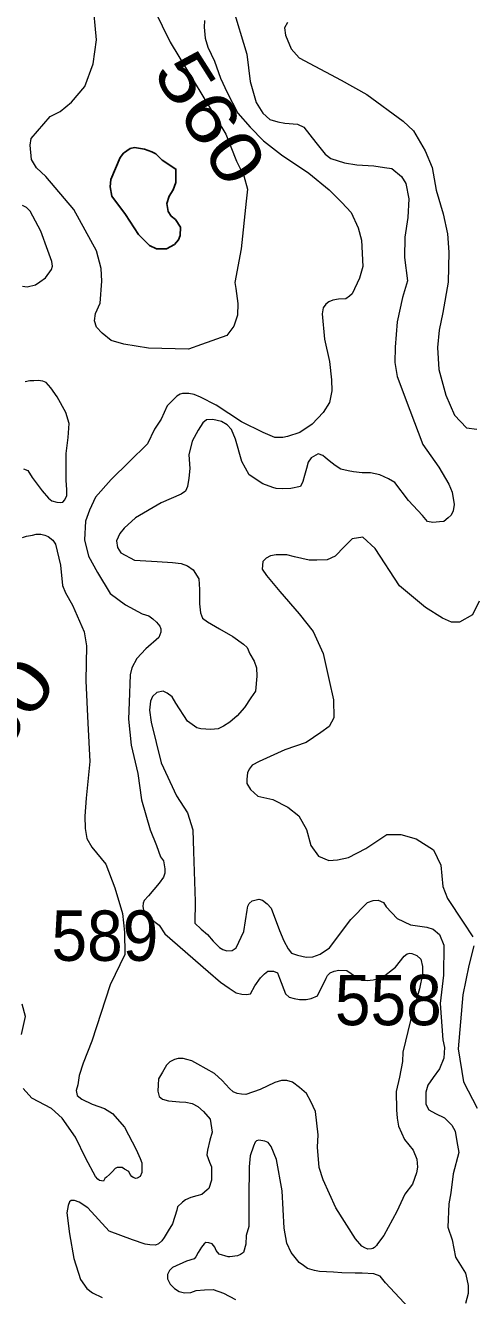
# Model space of a CAD drawing. Extents: x 445.4 to 500, y 8728.7 to 8784.
# Drawn here: x 475.988 to 477.407, y 8763.931 to 8767.967 of the extents above; entities that cross this region are included whole.
import ezdxf
from ezdxf.enums import TextEntityAlignment as Align

# ---------------------------------------------------------------- set-up
doc = ezdxf.new("R2010")
doc.units = 0
doc.header["$LTSCALE"] = 0.064
doc.layers.add('1', color=7, linetype='Continuous', lineweight=25)
doc.layers.add('2', color=7, linetype='Continuous', lineweight=13)
doc.layers.add('21', color=7, linetype='Continuous')
doc.layers.add('61', color=7, linetype='Continuous')

msp = doc.modelspace()

# ---------------------------------------------------------------- linework, layer by layer
at = {"layer": '1'}
msp.add_lwpolyline([(476.2891, 8767.5469), (476.259, 8767.477), (476.2574, 8767.4537), (476.2624, 8767.4237), (476.3058, 8767.3654), (476.3475, 8767.3021), (476.3825, 8767.2671), (476.4042, 8767.2571), (476.4359, 8767.2571), (476.4609, 8767.2704), (476.4742, 8767.2854), (476.4793, 8767.2987), (476.4809, 8767.3254), (476.4642, 8767.3504), (476.4509, 8767.3604), (476.4409, 8767.3754), (476.4375, 8767.4003), (476.4442, 8767.4237), (476.4576, 8767.4437), (476.4659, 8767.467), (476.4659, 8767.4936), (476.4659, 8767.5103), (476.4225, 8767.5386), (476.4025, 8767.5586), (476.3892, 8767.5653), (476.3658, 8767.5736), (476.3341, 8767.5786), (476.3208, 8767.5753), (476.2991, 8767.5603)], close=True, dxfattribs=at)
at = {"layer": '2'}
for points in [[(476.3972, 8768.0175), (476.4473, 8767.9131), (476.6242, 8767.6215), (476.6578, 8767.5353), (476.681, 8767.4884), (476.6927, 8767.4468), (476.6893, 8767.4085), (476.6727, 8767.2569), (476.6526, 8767.1503), (476.656, 8767.1303), (476.6626, 8767.0836), (476.6609, 8767.046), (476.6492, 8767.0111), (476.6275, 8766.9811), (476.5474, 8766.9527), (476.5057, 8766.9378), (476.3789, 8766.9411), (476.3005, 8766.9544), (476.2605, 8766.9661), (476.2321, 8766.9894), (476.2138, 8767.0077), (476.2071, 8767.0277), (476.2105, 8767.051), (476.2255, 8767.0844), (476.2305, 8767.1543), (476.2288, 8767.1943), (476.2137, 8767.2504), (476.142, 8767.382), (476.0536, 8767.4869), (476.0232, 8767.5144), (476.0082, 8767.5411), (476.0032, 8767.5861), (476.0066, 8767.6077), (476.0666, 8767.6777), (476.0983, 8767.6927), (476.135, 8767.7227), (476.1767, 8767.7727), (476.2034, 8767.8443), (476.2134, 8767.9209), (476.2018, 8768.0454)], [(476.6449, 8768.0251), (476.6912, 8767.8756), (476.7017, 8767.7882), (476.7202, 8767.722), (476.7418, 8767.6881), (476.7634, 8767.6681), (476.7896, 8767.6604), (476.8112, 8767.6558), (476.8513, 8767.6527), (476.8713, 8767.6434), (476.9099, 8767.5942), (476.9392, 8767.5572), (476.9577, 8767.5433), (477.0009, 8767.5295), (477.0394, 8767.5233), (477.0934, 8767.5202), (477.1274, 8767.5156), (477.1505, 8767.5125), (477.1813, 8767.4863), (477.1952, 8767.4648), (477.2045, 8767.4155), (477.2018, 8767.3559), (477.1926, 8767.2943), (477.191, 8767.2296), (477.2003, 8767.1556), (477.1848, 8767.1017), (477.1679, 8767.0247)], [(476.5566, 8767.9823), (476.5551, 8767.9609), (476.5588, 8767.926), (476.567, 8767.8971), (476.5878, 8767.8534), (476.6078, 8767.7986), (476.6287, 8767.7535), (476.6621, 8767.6875), (476.7014, 8767.6438), (476.7437, 8767.6001), (476.8013, 8767.5558), (476.8881, 8767.4972), (476.9526, 8767.4439)], [(476.8201, 8767.9754), (476.8104, 8767.9587), (476.8132, 8767.9351), (476.8312, 8767.8921), (476.8567, 8767.8634), (476.9901, 8767.7926), (477.072, 8767.7468), (477.1873, 8767.6622), (477.2192, 8767.6317), (477.2568, 8767.5679), (477.279, 8767.5152), (477.2917, 8767.4434), (477.3139, 8767.3685), (477.3278, 8767.3047), (477.332, 8767.2465), (477.3292, 8767.1508), (477.3124, 8767.054), (477.3013, 8766.9985), (477.2958, 8766.943), (477.2999, 8766.8737), (477.3222, 8766.7918), (477.3499, 8766.728), (477.3874, 8766.6878), (477.421, 8766.6841)], [(476.9526, 8767.4439), (476.9927, 8767.4039), (477.0224, 8767.3727), (477.0439, 8767.3238), (477.0545, 8767.2847), (477.059, 8767.201), (477.0486, 8767.1632), (477.0256, 8767.1135), (477.0167, 8767.1061), (477.0048, 8767.098), (476.9818, 8767.0965), (476.9638, 8767.0932), (476.9512, 8767.088), (476.9416, 8767.0813), (476.9327, 8767.0694), (476.9297, 8767.0502), (476.9371, 8766.9703), (476.9527, 8766.8984), (476.9594, 8766.8406), (476.9609, 8766.8058), (476.9527, 8766.769), (476.9334, 8766.7364), (476.8985, 8766.7001), (476.8592, 8766.6734), (476.8198, 8766.6608), (476.805, 8766.6579), (476.7798, 8766.6579), (476.7427, 8766.6734), (476.6736, 8766.7068), (476.5939, 8766.7597), (476.5441, 8766.7856), (476.5234, 8766.7938), (476.507, 8766.7975), (476.4952, 8766.7975), (476.487, 8766.7975), (476.4796, 8766.7952), (476.4692, 8766.7886), (476.438, 8766.7582), (476.4195, 8766.7152), (476.3984, 8766.6836), (476.3754, 8766.6377), (476.3175, 8766.5806), (476.2604, 8766.5243), (476.2104, 8766.4682), (476.1919, 8766.4267), (476.1785, 8766.3911), (476.1763, 8766.3326), (476.1889, 8766.2807), (476.2171, 8766.2289), (476.2572, 8766.1623), (476.3062, 8766.1259), (476.3588, 8766.0971), (476.3804, 8766.0911), (476.3922, 8766.0815), (476.4048, 8766.0704), (476.4152, 8766.0585), (476.4185, 8766.0497), (476.4185, 8766.0386), (476.4118, 8766.0223), (476.3703, 8765.986), (476.3421, 8765.9556), (476.3257, 8765.9252), (476.3205, 8765.9037), (476.3176, 8765.8163), (476.3153, 8765.7624), (476.3242, 8765.6801), (476.345, 8765.5905), (476.3569, 8765.5061), (476.3844, 8765.4113), (476.4044, 8765.3616), (476.4171, 8765.3254), (476.426, 8765.3121), (476.4304, 8765.2869), (476.4304, 8765.2735), (476.426, 8765.2602), (476.4126, 8765.2417), (476.3785, 8765.2017), (476.3651, 8765.1868), (476.3622, 8765.1779), (476.3607, 8765.1676), (476.3629, 8765.1557), (476.3711, 8765.1431), (476.3822, 8765.1313), (476.4126, 8765.1083), (476.4312, 8765.081), (476.5677, 8764.9609), (476.607, 8764.9269), (476.6345, 8764.9083), (476.6575, 8764.8928), (476.6746, 8764.8891), (476.6894, 8764.8883), (476.7028, 8764.8898), (476.7161, 8764.915), (476.7339, 8764.9409), (476.7465, 8764.9535), (476.7577, 8764.9617), (476.7753, 8764.9624), (476.7887, 8764.9572), (476.7946, 8764.9402), (476.8132, 8764.8898), (476.825, 8764.8794)], [(475.979, 8767.1383), (475.9942, 8767.1359), (476.0199, 8767.1429), (476.0339, 8767.1523), (476.0526, 8767.1651), (476.0712, 8767.1907), (476.0747, 8767.2012), (476.0724, 8767.2164), (476.0596, 8767.2514), (476.0374, 8767.3132), (476.0035, 8767.3761), (475.9919, 8767.3878), (475.979, 8767.3948)], [(477.1679, 8767.0247), (477.1617, 8766.9449), (477.1602, 8766.8956), (477.1679, 8766.851), (477.208, 8766.7447), (477.2496, 8766.6353), (477.3005, 8766.5629), (477.3317, 8766.5095), (477.3425, 8766.4833), (477.3487, 8766.4448), (477.3456, 8766.4248), (477.3394, 8766.4109), (477.3302, 8766.4017), (477.3163, 8766.3909), (477.3024, 8766.3893), (477.2808, 8766.3878), (477.2638, 8766.3909), (477.2484, 8766.4094), (477.2037, 8766.4571), (477.1605, 8766.5141), (477.1404, 8766.5264), (477.1127, 8766.5387), (477.0834, 8766.5449), (477.0572, 8766.5449), (477.0294, 8766.548), (477.0124, 8766.5511), (476.9893, 8766.5572), (476.9708, 8766.568), (476.9523, 8766.5834), (476.9399, 8766.5942), (476.9322, 8766.6004), (476.9168, 8766.605), (476.8952, 8766.5927), (476.8859, 8766.5788), (476.8798, 8766.5588), (476.8736, 8766.5372), (476.869, 8766.5172), (476.8613, 8766.5018), (476.8304, 8766.4956), (476.8042, 8766.4941), (476.7842, 8766.4956), (476.7734, 8766.4987), (476.7414, 8766.5099), (476.6982, 8766.5391), (476.6751, 8766.5807), (476.6551, 8766.6516), (476.6427, 8766.6824), (476.6288, 8766.6978), (476.6103, 8766.7085), (476.5826, 8766.7147), (476.5625, 8766.7132), (476.5517, 8766.7039), (476.5363, 8766.6808), (476.5178, 8766.6454), (476.507, 8766.6023), (476.5101, 8766.5591), (476.507, 8766.5283), (476.5024, 8766.5022), (476.4962, 8766.4867), (476.4823, 8766.4775), (476.4191, 8766.4498), (476.3373, 8766.402), (476.3019, 8766.3697), (476.288, 8766.3527), (476.2772, 8766.3296), (476.2803, 8766.3081), (476.2911, 8766.2911), (476.3342, 8766.268), (476.4067, 8766.2634), (476.4546, 8766.2603), (476.4823, 8766.2572), (476.5024, 8766.2495), (476.5209, 8766.2372), (476.5381, 8766.2086), (476.5411, 8766.1747), (476.5411, 8766.1285), (476.5442, 8766.1008), (476.5504, 8766.0839), (476.5658, 8766.0715), (476.6044, 8766.05), (476.646, 8766.0253), (476.68, 8766.0007), (476.6923, 8765.9899), (476.7, 8765.9699), (476.7139, 8765.9468), (476.7216, 8765.9252), (476.7231, 8765.899), (476.7188, 8765.8517), (476.7033, 8765.8301), (476.6833, 8765.7993), (476.6601, 8765.7731), (476.637, 8765.7531), (476.617, 8765.7408), (476.6, 8765.7315), (476.5769, 8765.73), (476.5445, 8765.7315), (476.5321, 8765.7346), (476.5028, 8765.7562), (476.4658, 8765.8132), (476.4535, 8765.8332), (476.438, 8765.8455)], [(475.9818, 8766.5583), (475.9965, 8766.5521), (476.0095, 8766.5307), (476.0416, 8766.4879), (476.0617, 8766.4649), (476.0724, 8766.4559), (476.0876, 8766.4525), (476.1, 8766.4514), (476.1074, 8766.4525), (476.1136, 8766.4593), (476.1198, 8766.4732), (476.1198, 8766.4924), (476.1176, 8766.5205), (476.1176, 8766.6067), (476.1243, 8766.6574), (476.1277, 8766.7018), (476.117, 8766.7367), (476.0894, 8766.7868), (476.0691, 8766.8155), (476.0537, 8766.8317), (476.0435, 8766.8368), (476.0289, 8766.8385), (476.0153, 8766.8379), (476.0029, 8766.8374), (475.9871, 8766.8345)], [(475.9792, 8766.3396), (475.992, 8766.3444), (476.0113, 8766.3476), (476.0225, 8766.3508), (476.0369, 8766.3508), (476.0497, 8766.3476), (476.0609, 8766.3428), (476.0754, 8766.3316), (476.0834, 8766.3188), (476.0994, 8766.2516), (476.1058, 8766.1876), (476.1154, 8766.1636), (476.1379, 8766.1252), (476.1747, 8766.0404), (476.1827, 8765.9956), (476.1797, 8765.8841), (476.1861, 8765.7497), (476.1925, 8765.6281), (476.1813, 8765.5113), (476.1765, 8765.454), (476.1781, 8765.4156), (476.1829, 8765.3836), (476.1989, 8765.3564), (476.2438, 8765.302), (476.2726, 8765.2268), (476.2967, 8765.1452), (476.3031, 8765.086), (476.3034, 8765.0145), (476.2569, 8764.9185), (476.1992, 8764.7392), (476.1718, 8764.6694), (476.159, 8764.631), (476.1542, 8764.6006), (476.1494, 8764.583), (476.1526, 8764.567), (476.167, 8764.5558), (476.2006, 8764.5398), (476.2391, 8764.5254), (476.2647, 8764.5094), (476.3032, 8764.4662), (476.3401, 8764.3958), (476.3529, 8764.367), (476.3577, 8764.3526), (476.3577, 8764.3382), (476.3577, 8764.3222), (476.3529, 8764.3094), (476.3433, 8764.3046), (476.3385, 8764.303), (476.3304, 8764.3062), (476.3256, 8764.3094), (476.3208, 8764.3158), (476.316, 8764.3254), (476.3032, 8764.3334), (476.2952, 8764.3382), (476.2872, 8764.3382), (476.2792, 8764.3382), (476.2728, 8764.335), (476.2647, 8764.3254), (476.2551, 8764.3158), (476.2455, 8764.3078), (476.2407, 8764.303), (476.2359, 8764.295), (476.2231, 8764.2966), (476.2183, 8764.3014), (476.2103, 8764.3094), (476.1798, 8764.367), (476.1478, 8764.4342), (476.1045, 8764.495), (476.0709, 8764.5254), (476.0084, 8764.559), (475.9811, 8764.5894)], [(477.4276, 8766.1375), (477.407, 8766.0937), (477.3658, 8766.0705), (477.34, 8766.0705), (477.3116, 8766.0834), (477.2575, 8766.1169), (477.175, 8766.1864), (477.0977, 8766.3048), (477.0591, 8766.3408), (477.0252, 8766.3352), (477.0006, 8766.3107), (476.9715, 8766.28), (476.9454, 8766.2693)], [(476.9454, 8766.2693), (476.9132, 8766.2678), (476.8886, 8766.2678), (476.8426, 8766.2785), (476.8181, 8766.2846), (476.8012, 8766.2846), (476.7843, 8766.2846), (476.7659, 8766.2816), (476.7521, 8766.2739), (476.7414, 8766.2632), (476.7398, 8766.2387), (476.7536, 8766.2188), (476.7951, 8766.1682), (476.8567, 8766.0967), (476.9012, 8766.0415), (476.9334, 8765.971), (476.9518, 8765.8852), (476.9656, 8765.8239), (476.9672, 8765.7673), (476.9518, 8765.7397), (476.9258, 8765.7198), (476.8791, 8765.6881), (476.8116, 8765.6651), (476.7303, 8765.6284), (476.7073, 8765.6161), (476.6981, 8765.6038), (476.6935, 8765.5916), (476.6904, 8765.5717), (476.6904, 8765.5579), (476.7027, 8765.5395), (476.7257, 8765.518), (476.7732, 8765.5073), (476.8208, 8765.4828), (476.8561, 8765.4552), (476.8806, 8765.4123), (476.8938, 8765.3612), (476.9183, 8765.3274), (476.9506, 8765.3137), (476.9782, 8765.3152), (477.0135, 8765.3229), (477.0687, 8765.352), (477.1346, 8765.3964), (477.1791, 8765.3964), (477.2282, 8765.3826), (477.2835, 8765.3474), (477.3065, 8765.2983), (477.3126, 8765.2309), (477.3279, 8765.1926), (477.377, 8765.1176), (477.4077, 8765.0716)], [(476.438, 8765.8455), (476.4257, 8765.8517), (476.4056, 8765.847), (476.3918, 8765.8347), (476.3856, 8765.8193), (476.3825, 8765.7916), (476.3871, 8765.7531), (476.4195, 8765.6237), (476.4673, 8765.519), (476.5027, 8765.4654), (476.5196, 8765.4115), (476.5212, 8765.3422), (476.5273, 8765.1835), (476.5258, 8765.1142), (476.5458, 8765.0957), (476.5659, 8765.0788), (476.5844, 8765.0572), (476.6044, 8765.0372), (476.6152, 8765.031), (476.6276, 8765.0264), (476.6446, 8765.0279), (476.6569, 8765.0357), (476.6816, 8765.088), (476.6924, 8765.1558), (476.6939, 8765.1681), (476.6985, 8765.1774), (476.7078, 8765.1851), (476.7294, 8765.1912), (476.7402, 8765.1881), (476.7556, 8765.1758), (476.7679, 8765.162), (476.7942, 8765.0911), (476.808, 8765.0588), (476.8219, 8765.0326), (476.8327, 8765.0187), (476.8512, 8765.0125), (476.879, 8765.0064), (476.9006, 8765.0079), (476.9237, 8765.0156), (476.953, 8765.0357), (477.0209, 8765.1265), (477.0733, 8765.1804), (477.0918, 8765.1866), (477.1073, 8765.1881), (477.1242, 8765.1804), (477.1335, 8765.1666), (477.1674, 8765.1296), (477.2106, 8765.1096), (477.2624, 8765.1013), (477.2825, 8765.0951), (477.3025, 8765.0782), (477.3164, 8765.0443), (477.3149, 8764.9488), (477.3041, 8764.8595), (477.313, 8764.7444), (477.3176, 8764.7197), (477.3161, 8764.6858), (477.3022, 8764.6519), (477.2822, 8764.6242), (477.2652, 8764.5996), (477.259, 8764.578), (477.259, 8764.5549), (477.259, 8764.5395), (477.2683, 8764.521), (477.2899, 8764.5102), (477.3176, 8764.4964), (477.3408, 8764.4733), (477.3516, 8764.4532), (477.3577, 8764.4209), (477.3639, 8764.3855), (477.3456, 8764.3179), (477.3379, 8764.2579), (477.3318, 8764.2224), (477.3287, 8764.1485), (477.3426, 8764.1085), (477.3534, 8764.053), (477.3842, 8764.0022), (477.3888, 8763.9837), (477.3935, 8763.9637), (477.3935, 8763.9375), (477.3842, 8763.9067)], [(477.4108, 8765.0425), (477.3951, 8764.9799), (477.3767, 8764.8864), (477.3614, 8764.7148), (477.3782, 8764.6106), (477.4216, 8764.5269)], [(476.825, 8764.8794), (476.8406, 8764.8757), (476.8584, 8764.872), (476.8792, 8764.872), (476.8955, 8764.875), (476.9156, 8764.8839), (476.9423, 8764.9394), (476.9467, 8764.9483), (476.9549, 8764.9572), (476.9675, 8764.9617), (476.9831, 8764.9654), (477.0083, 8764.9639), (477.0217, 8764.955), (477.0395, 8764.9424), (477.0551, 8764.9335), (477.0729, 8764.9328), (477.0922, 8764.935), (477.1189, 8764.9409), (477.1627, 8764.975), (477.1901, 8765.0098), (477.1996, 8765.0172), (477.2077, 8765.0187), (477.2144, 8765.018), (477.2307, 8765.012), (477.2434, 8765.0002), (477.2478, 8764.9765), (477.2478, 8764.952), (477.2389, 8764.9061), (477.2099, 8764.8048), (477.1862, 8764.7047), (477.1846, 8764.6753), (477.175, 8764.6249), (477.1646, 8764.5797), (477.1661, 8764.5219), (477.1683, 8764.4952), (477.1721, 8764.4695), (477.1914, 8764.4272), (477.2188, 8764.3931), (477.2307, 8764.365), (477.2322, 8764.3398), (477.2292, 8764.3213), (477.2166, 8764.285), (477.1921, 8764.2538), (477.1668, 8764.1984), (477.1252, 8764.1221), (477.1059, 8764.0962), (477.1022, 8764.0902), (477.0955, 8764.0843), (477.0903, 8764.0813), (477.0866, 8764.0799), (477.0747, 8764.0791), (477.0651, 8764.0828), (477.0554, 8764.088), (477.0354, 8764.1117), (476.9738, 8764.2103), (476.9326, 8764.2989), (476.9207, 8764.3381), (476.9148, 8764.4026), (476.9177, 8764.4419), (476.9089, 8764.5166), (476.8941, 8764.5484), (476.8807, 8764.5736), (476.8585, 8764.5929), (476.8355, 8764.6092), (476.8177, 8764.6144), (476.8006, 8764.6144), (476.7798, 8764.6085), (476.7331, 8764.5862), (476.6881, 8764.57), (476.674, 8764.5708), (476.6599, 8764.5737), (476.648, 8764.5782), (476.6354, 8764.5893), (476.6131, 8764.6145), (476.5886, 8764.6374), (476.5352, 8764.6663), (476.5166, 8764.6767), (476.5003, 8764.6812), (476.4884, 8764.6849), (476.4729, 8764.6849), (476.4617, 8764.6819), (476.4462, 8764.6745), (476.4358, 8764.6634), (476.4231, 8764.6411), (476.4105, 8764.6197), (476.4091, 8764.6004), (476.4083, 8764.5804), (476.4128, 8764.5641), (476.4231, 8764.5559), (476.4424, 8764.55), (476.4773, 8764.547), (476.4974, 8764.5463), (476.5174, 8764.5419), (476.5352, 8764.5322), (476.5537, 8764.5167), (476.5745, 8764.4915), (476.5767, 8764.4781), (476.5805, 8764.4507), (476.5738, 8764.4256), (476.5657, 8764.393), (476.5635, 8764.379)], [(475.9763, 8764.7606), (475.9891, 8764.8177), (475.9779, 8764.8577)], [(476.8567, 8764.0361), (476.832, 8764.0684), (476.8182, 8764.0977), (476.8089, 8764.1454), (476.8027, 8764.264), (476.7849, 8764.3634), (476.7679, 8764.405), (476.7587, 8764.4173), (476.7479, 8764.4219), (476.7294, 8764.425), (476.7216, 8764.4235), (476.717, 8764.4189), (476.7124, 8764.4065), (476.7016, 8764.3757), (476.6985, 8764.3403), (476.697, 8764.2417), (476.697, 8764.1512), (476.6893, 8764.1219), (476.6878, 8764.0942), (476.68, 8764.068), (476.6708, 8764.0618), (476.6615, 8764.0572), (476.6369, 8764.0541), (476.6322, 8764.0541), (476.6029, 8764.0634), (476.5937, 8764.0741), (476.589, 8764.0849), (476.5813, 8764.0957), (476.5705, 8764.0988), (476.5613, 8764.1003), (476.5551, 8764.0957), (476.5474, 8764.0849), (476.5366, 8764.068), (476.5289, 8764.0541), (476.5243, 8764.048), (476.4996, 8764.0403), (476.4549, 8764.0202), (476.4456, 8764.011), (476.4394, 8763.9987), (476.4394, 8763.9848), (476.4472, 8763.9679), (476.461, 8763.954), (476.4765, 8763.9448), (476.4934, 8763.9401), (476.5135, 8763.9417), (476.5304, 8763.9478), (476.5567, 8763.9494), (476.5844, 8763.9509), (476.6168, 8763.9386), (476.6554, 8763.9186)], [(476.5635, 8764.379), (476.5724, 8764.3553), (476.5783, 8764.3404), (476.5783, 8764.2982), (476.5701, 8764.2715), (476.5649, 8764.2671), (476.5479, 8764.253), (476.5323, 8764.2478), (476.5137, 8764.2426), (476.4967, 8764.236), (476.487, 8764.2278), (476.4712, 8764.2133), (476.469, 8764.2029), (476.4549, 8764.1592), (476.4415, 8764.137), (476.4282, 8764.1162), (476.4215, 8764.1058), (476.4111, 8764.0962), (476.4007, 8764.0918), (476.3829, 8764.0925), (476.3681, 8764.0947), (476.328, 8764.1088), (476.2545, 8764.1355), (476.1863, 8764.2103), (476.1584, 8764.2282), (476.1443, 8764.2334), (476.1339, 8764.2334), (476.128, 8764.2289), (476.1235, 8764.2178), (476.1198, 8764.1941), (476.1287, 8764.1274), (476.1421, 8764.0491), (476.1629, 8763.9824), (476.1837, 8763.9535), (476.2008, 8763.9401), (476.2319, 8763.9253)], [(477.2053, 8763.8928), (477.1313, 8763.9714), (477.1143, 8763.9929), (477.0942, 8764.0006), (477.0572, 8764.0022), (477.0341, 8764.0022), (476.9924, 8764.0037), (476.9662, 8764.0053), (476.9215, 8764.0083), (476.9061, 8764.0114), (476.8829, 8764.0176), (476.8706, 8764.0268), (476.8567, 8764.0361)]]:
    msp.add_lwpolyline(points, dxfattribs=at)

# ---------------------------------------------------------------- texts
at = {"layer": '21', "width": 0.95}
for s, p in [('589', (476.071, 8764.9948)), ('558', (476.9703, 8764.7903))]:
    msp.add_text(s, height=0.16, dxfattribs=at).set_placement(p)
at = {"layer": '61'}
for rotation, width, p in [(302.354, 1.25, (476.5082, 8767.6297)), (52.14, 1.3, (475.9526, 8765.6946))]:
    msp.add_text('560', height=0.16, rotation=rotation, dxfattribs=dict(at, width=width)).set_placement(p, align=Align.CENTER)

doc.saveas('drawing.dxf')
